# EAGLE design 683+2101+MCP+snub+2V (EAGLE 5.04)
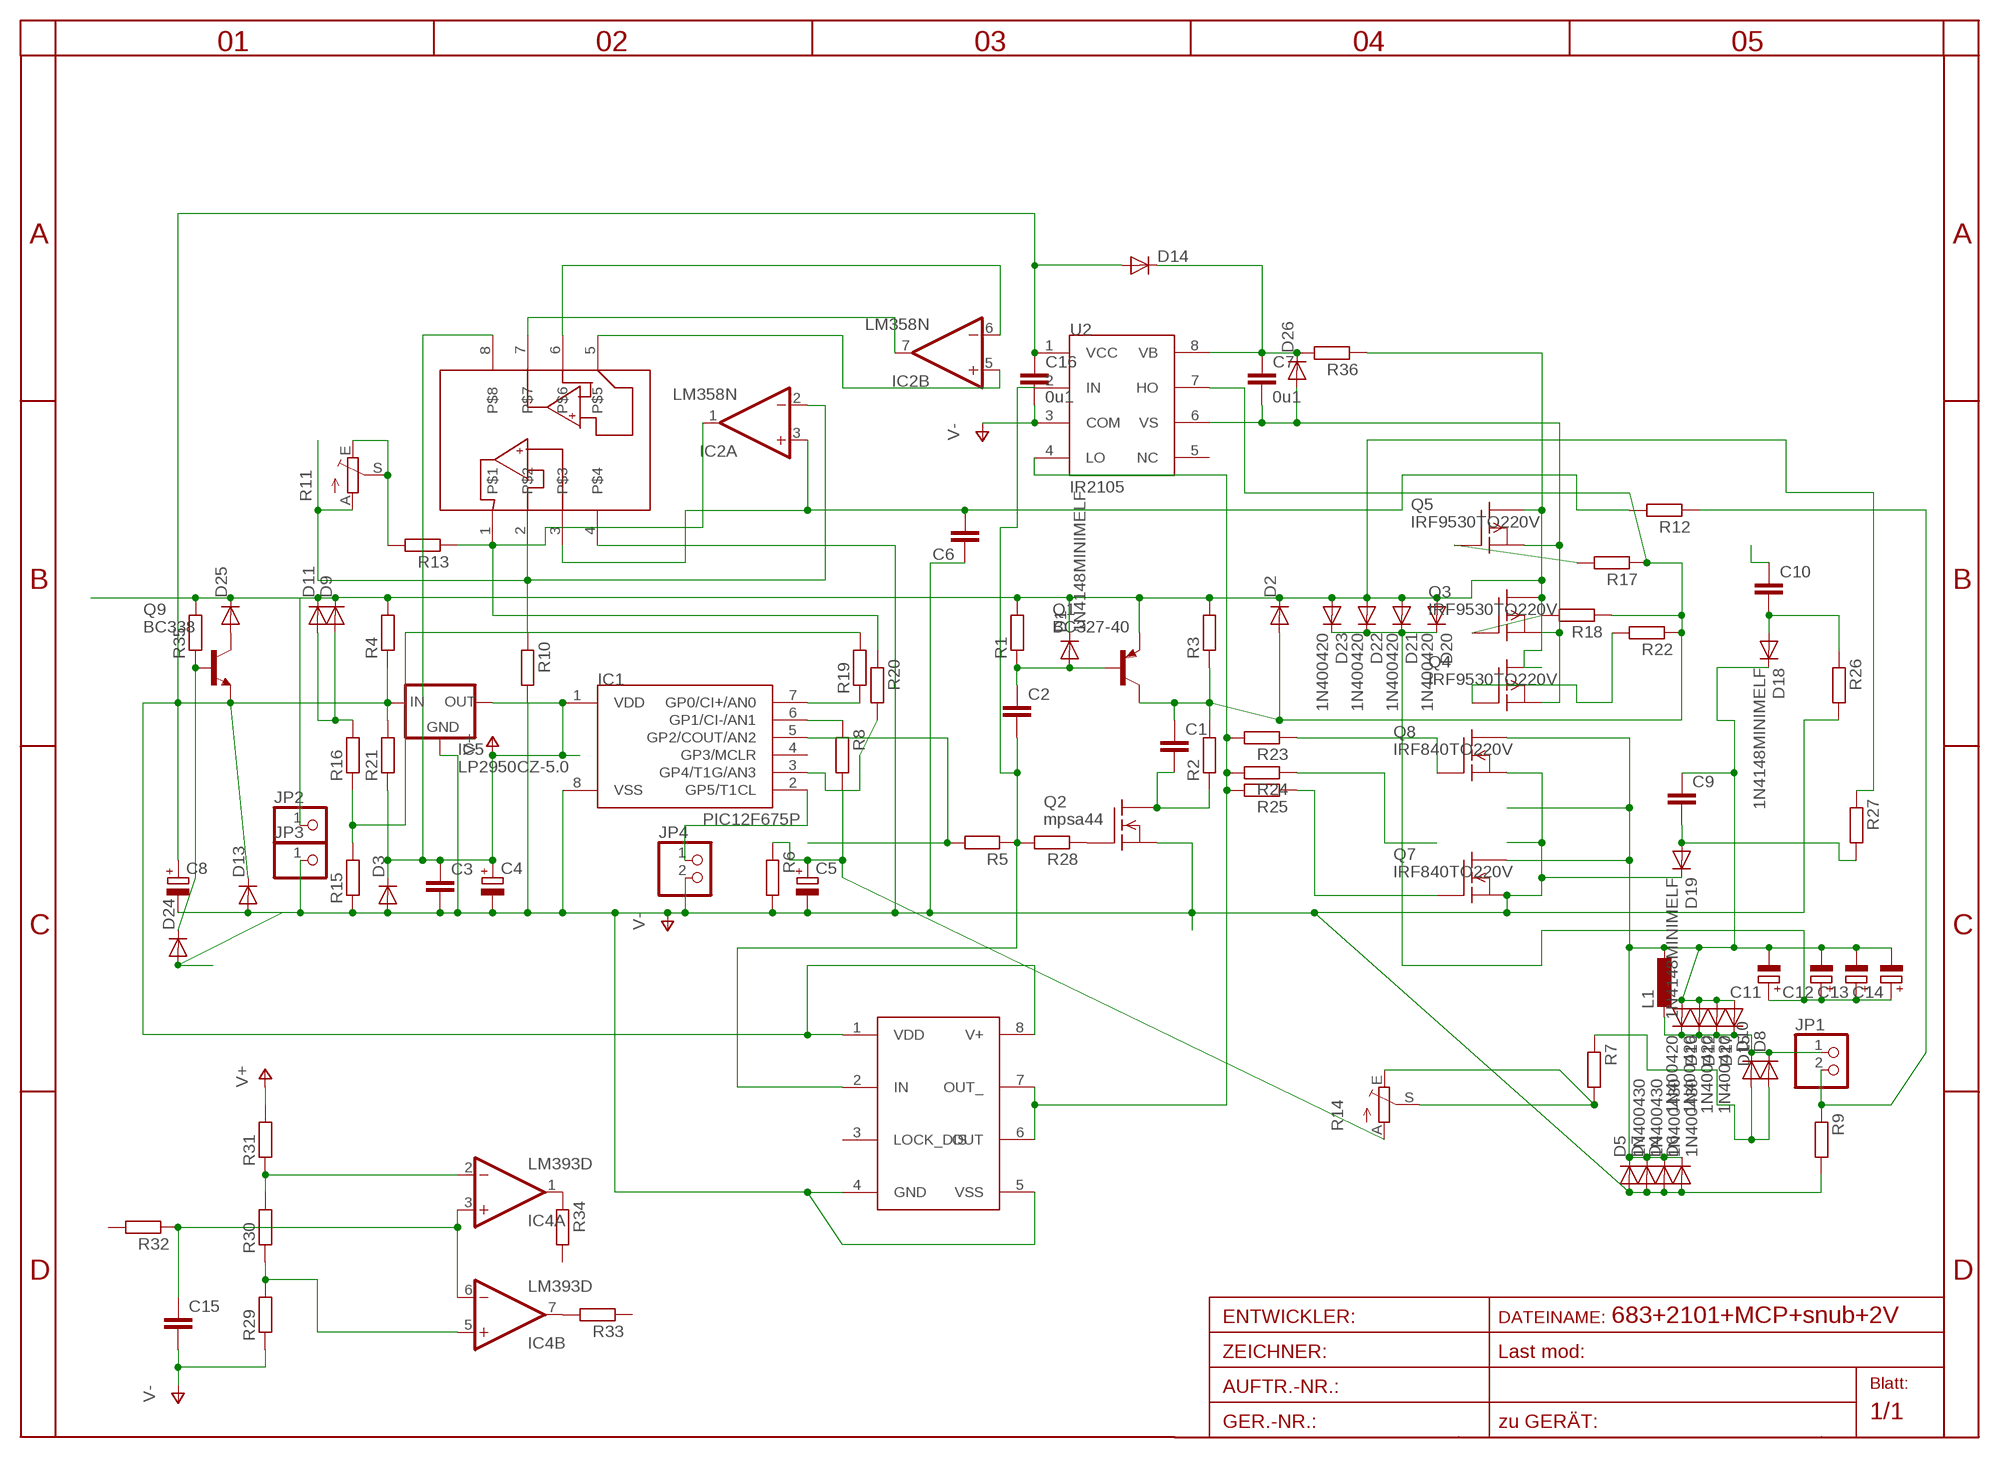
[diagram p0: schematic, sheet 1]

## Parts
C1  C-EU225-074X268  [C225-074X268]
C2  C-EU225-062X268  [C225-062X268]
C3  C-EU050-025X075  [C050-025X075]
C4  CPOL-EUE2.5-7  [E2,5-7]
C5  CPOL-EU5-13  [2,5-5-FLAT]
C6  C-EU025_050-025X075  [C025_050-025X075]
C7  0u1  C-EU050-030X075  [C050-030X075]
C8  CPOL-EU5-13  [2,5-5-FLAT]
C9  C-EUC1812  [C1812]
C10  C-EUC1812K  [C1812K]
C11  CPOL-EUSANYO_SMD_E7  [SANYO-OSCON_SMD_E7]
C12  CPOL-EUSANYO_SMD_E7  [SANYO-OSCON_SMD_E7]
C13  CPOL-EUSANYO_SMD_E7  [SANYO-OSCON_SMD_E7]
C14  CPOL-EUSANYO_SMD_E7  [SANYO-OSCON_SMD_E7]
C15  C-EU025-025X050  [C025-025X050]
C16  0u1  C-EU050-030X075  [C050-030X075]
D1  1N4148MINIMELF  [MINIMELF]
D2  DIODE-D-5  [D-5]
D3  DIODE-D-2.5  [D-2.5]
D4  1N400430  [DO41-30]
D5  1N400430  [DO41-30]
D6  1N400430  [DO41-30]
D7  1N400430  [DO41-30]
D8  DIODE-D-2.5  [D-2.5]
D9  DIODE-D-2.5  [D-2.5]
D10  DIODE-DO41-30  [DO41-30]
D11  DIODE-D-10  [D-10]
D12  1N400420  [DO41-20]
D13  DIODE-D-2.5  [D-2.5]
D14  DIODE-D-5  [D-5]
D15  1N400420  [DO41-20]
D16  1N400420  [DO41-20]
D17  1N400420  [DO41-20]
D18  1N4148MINIMELF  [MINIMELF]
D19  1N4148MINIMELF  [MINIMELF]
D20  1N400420  [DO41-20]
D21  1N400420  [DO41-20]
D22  1N400420  [DO41-20]
D23  1N400420  [DO41-20]
D24  DIODE-D-2.5  [D-2.5]
D25  DIODE-D-2.5  [D-2.5]
D26  DIODE-D-2.5  [D-2.5]
IC1  PIC12F675P  [DIL8]
IC2  LM358N  [DIL08]
IC3  TC4432X  [SO-08]
IC4  LM393D  [SO08]
IC5  LP2950CZ-5.0  [TO92]
JP1  PINHD-1X2  [1X02]
JP2  PINHD-1X1  [1X01]
JP3  PINHD-1X1  [1X01]
JP4  PINHD-1X2  [1X02]
L1  L-EU0204/7  [0204/7]
Q1  BC327-40  [TO92-EBC]
Q2  mpsa44  TN0604N3  [TO-92]
Q3  IRF9530TO220V  [TO220V]
Q4  IRF9530TO220V  [TO220V]
Q5  IRF9530TO220V  [TO220V]
Q7  IRF840TO220V  [TO220V]
Q8  IRF840TO220V  [TO220V]
Q9  BC338  [TO92-EBC]
R1  R-EU_0204/2V  [0204V]
R2  R-EU_0207/25  [0207/25]
R3  R-EU_0204/2V  [0204V]
R4  R-EU_0207/10  [0207/10]
R5  R-EU_0207/40  [0207/40]
R6  R-EU_0207/10  [0207/10]
R7  R-EU_0207/15  [0207/15]
R8  R-EU_0207/10  [0207/10]
R9  R-EU_0207/10  [0207/10]
R10  R-EU_0207/15  [0207/15]
R11  TRIM_EU-CIP20C-4MM  [CIP20C-4MM]
R12  R-EU_0207/30  [0207/30]
R13  R-EU_0207/40  [0207/40]
R14  TRIM_EU-CIP20C-4MM  [CIP20C-4MM]
R15  R-EU_0204/5  [0204/5]
R16  R-EU_0207/25  [0207/25]
R17  R-EU_R1206  [R1206]
R18  R-EU_R1206  [R1206]
R19  R-EU_0204/5  [0204/5]
R20  R-EU_0204/5  [0204/5]
R21  R-EU_0207/10  [0207/10]
R22  R-EU_R1206  [R1206]
R23  R-EU_R1206  [R1206]
R24  R-EU_R1206  [R1206]
R25  R-EU_R1206  [R1206]
R26  R-EU_0207/25  [0207/25]
R27  R-EU_0207/30  [0207/30]
R28  R-EU_R0805  [R0805]
R29  R-EU_0204/5  [0204/5]
R30  R-EU_0204/5  [0204/5]
R31  R-EU_0204/5  [0204/5]
R32  R-EU_0204/5  [0204/5]
R33  R-EU_0204/5  [0204/5]
R34  R-EU_0204/2V  [0204V]
R35  R-EU_0207/10  [0207/10]
R36  R-EU_0204/2V  [0204V]
U2  IR2105  [DIL08]
U$1  MCP6042SOIC  [SO-08]

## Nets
BB: C2.2 IC3.2(IN) R5.1 R28.2 U2.2(IN)
DRAIN: C9.1 C11.- C12.- C13.- C14.- D4.C D5.C D6.C D7.C D12.A D15.A D16.A D17.A D18.C L1.1 Q7.2(D) Q8.2(D)
GATE: C1.1 D2.A Q1.C R2.2 R3.1 R17.1 R18.1 R22.1 U2.7(HO)
MPOINT: C5.+ R6.1 R8.2 R14.A
N$1: C1.2 Q2.3(D) R2.1
N$2: IC2.6(B:-IN) U$1.6
N$3: IC1.5(GP2/COUT/AN2) R5.2
N$4: Q3.1(G) R18.2
N$5: IC1.6(GP1/CI-/AN1) R8.1
N$6: IC2.2(A:-IN) R10.1 R11.A U$1.2
N$7: IC2.1(A:OUT) R13.1 R20.1 U$1.1
N$8: Q2.2(G) R28.1
N$9: C6.2 IC2.3(A:+IN) R12.2 U$1.3
N$10: R7.2 R14.E R14.S
N$11: Q5.1(G) R17.2
N$12: R15.2 R16.1 R19.2
N$13: D9.A D11.A R16.2
N$14: IC1.7(GP0/CI+/AN0) R19.1
N$15: IC1.2(GP5/T1CL) JP4.1
N$16: D8.A D10.A R7.1
N$17: IC1.3(GP4/T1G/AN3) R20.2
N$18: IC2.5(B:+IN) U$1.5
N$19: C15.1 IC4.3(A:+IN) IC4.6(B:-IN) R32.1
N$20: IC2.7(B:OUT) U$1.7
N$21: C7.2 D26.A Q3.3(S) Q4.3(S) Q5.3(S) U2.6(VS)
N$22: IC4.7(B:OUT) R33.2
N$23: Q4.1(G) R22.2
N$24: C10.2 D18.A R26.1
N$25: Q7.1(G) R25.1
N$26: R24.1
N$27: Q8.1(G) R23.1
N$28: C9.2 D19.A R27.2
N$29: R11.E R11.S R13.2
N$30: IC4.1(A:OUT) R34.1
N$31: C11.+ C12.+ C13.+ C14.+ D20.C D21.C D22.C D23.C
N$32: IC4.5(B:+IN) R29.2 R30.1
N$33: IC3.6(OUT) IC3.7(OUT_) R23.2 R24.2 R25.2 U2.4(LO)
N$34: IC4.2(A:-IN) R30.2 R31.1
N$35: D25.A Q9.C
N$36: D24.C Q9.B R35.1
N$37: C10.1
OUT+: D8.C D10.C D12.C D15.C D16.C D17.C JP1.1 L1.2
OUT-: JP1.2 R9.1 R12.1
TB: C2.1 D1.A Q1.B R1.1
V+: C3.1 C4.+ D3.C IC1.1(VDD) IC5.1(OUT) R21.1 R31.2 U$1.8
V-: C3.2 C4.- C5.- C6.1 C8.- C15.2 C16.2 D3.A D4.A D5.A D6.A D7.A D13.A D19.C D24.A IC1.8(VSS) IC3.4(GND) IC3.5(VSS) IC5.2(GND) JP3.1 JP4.2 Q2.1(S) Q7.3(S) Q8.3(S) R6.2 R9.2 R10.2 R15.1 R26.2 R29.1 U2.3(COM) U$1.4
VB: C7.1 D14.C D26.C R36.2 U2.8(VB)
VCC: C8.+ C16.1 D13.C D14.A IC3.1(VDD) IC3.8(V+) IC5.3(IN) Q9.E R4.1 R21.2 U2.1(VCC)
VIN: D1.C D2.C D9.C D11.C D20.A D21.A D22.A D23.A JP2.1 Q1.E Q3.2(D) Q4.2(D) Q5.2(D) R1.2 R3.2 R4.2 R27.1 R36.1
VIN1: D25.C R35.2
Unconnected: IC1.4(GP3/MCLR) IC3.3(LOCK_DIS) R32.2 R33.1 R34.2 U2.5(NC)

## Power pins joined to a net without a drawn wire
V+: IC2.8(P:V+) IC4.8(P:V+)
V-: IC2.4(P:V-) IC4.4(P:V-)

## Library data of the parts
C1-C3 C6 C7 C9 C10 C15 C16 = rcl-2:C-EU: CAPACITOR, European symbol
C4 C5 C8 C11-C14 = rcl-2:CPOL-EU: POLARIZED CAPACITOR, European symbol
D1 D18 D19 = diode-1:1N4148: DIODE
D2 D3 D8-D11 D13 D14 D24-D26 = diode-1:DIODE-: DIODE
D4-D7 D12 D15-D17 D20-D23 = diode-1:1N4004: DIODE
IC1 = microchip-5:PIC12F6*: uPC nW 1k Program Flash memory 2x Timer Comparator 10b A/D converter/ 4xIN
IC2 = linear:LM358: OP AMP also LM158; LM258; LM2904 Source: http://cache.national.com/ds/LM/LM158.pdf
IC3 = microchip:TC4432
IC4 = linear:LM393: COMPARATOR
IC5 = v-reg:LP2950?*: Source: http://cache.national.com/ds/LP/LP2950.pdf
JP1 JP4 = pinhead:PINHD-1X2: PIN HEADER
JP2 JP3 = pinhead:PINHD-1X1: PIN HEADER
L1 = rcl-2:L-EU: INDUCTOR, European symbol
Q1 = transistor-pnp:BC327*: PNP Transistror
Q2 = transistor-fet:TN0604N3: N-Channel Enhancement MOSFET 40V; 4A; 0,75Ohm
Q3-Q5 = transistor-fet:IRF9530: P-Channel Enhancement MOSFET (HEXFET); -100V; -12A; 0,3Ohm
Q7 Q8 = transistor-fet:IRF840: N-Channel Enhancement MOSFET (HEXFET); 500V; 8A; 0,85Ohm
Q9 = transistor-npn:BC338*: NPN Transistor
R1-R10 R12 R13 R15-R36 = rcl-2:R-EU_: RESISTOR, European symbol
R11 R14 = pot:TRIM_EU-: POTENTIOMETER
U2 = irf-2:IR2105: Half bridge driver
U$1 = microchip-3:MCP6042

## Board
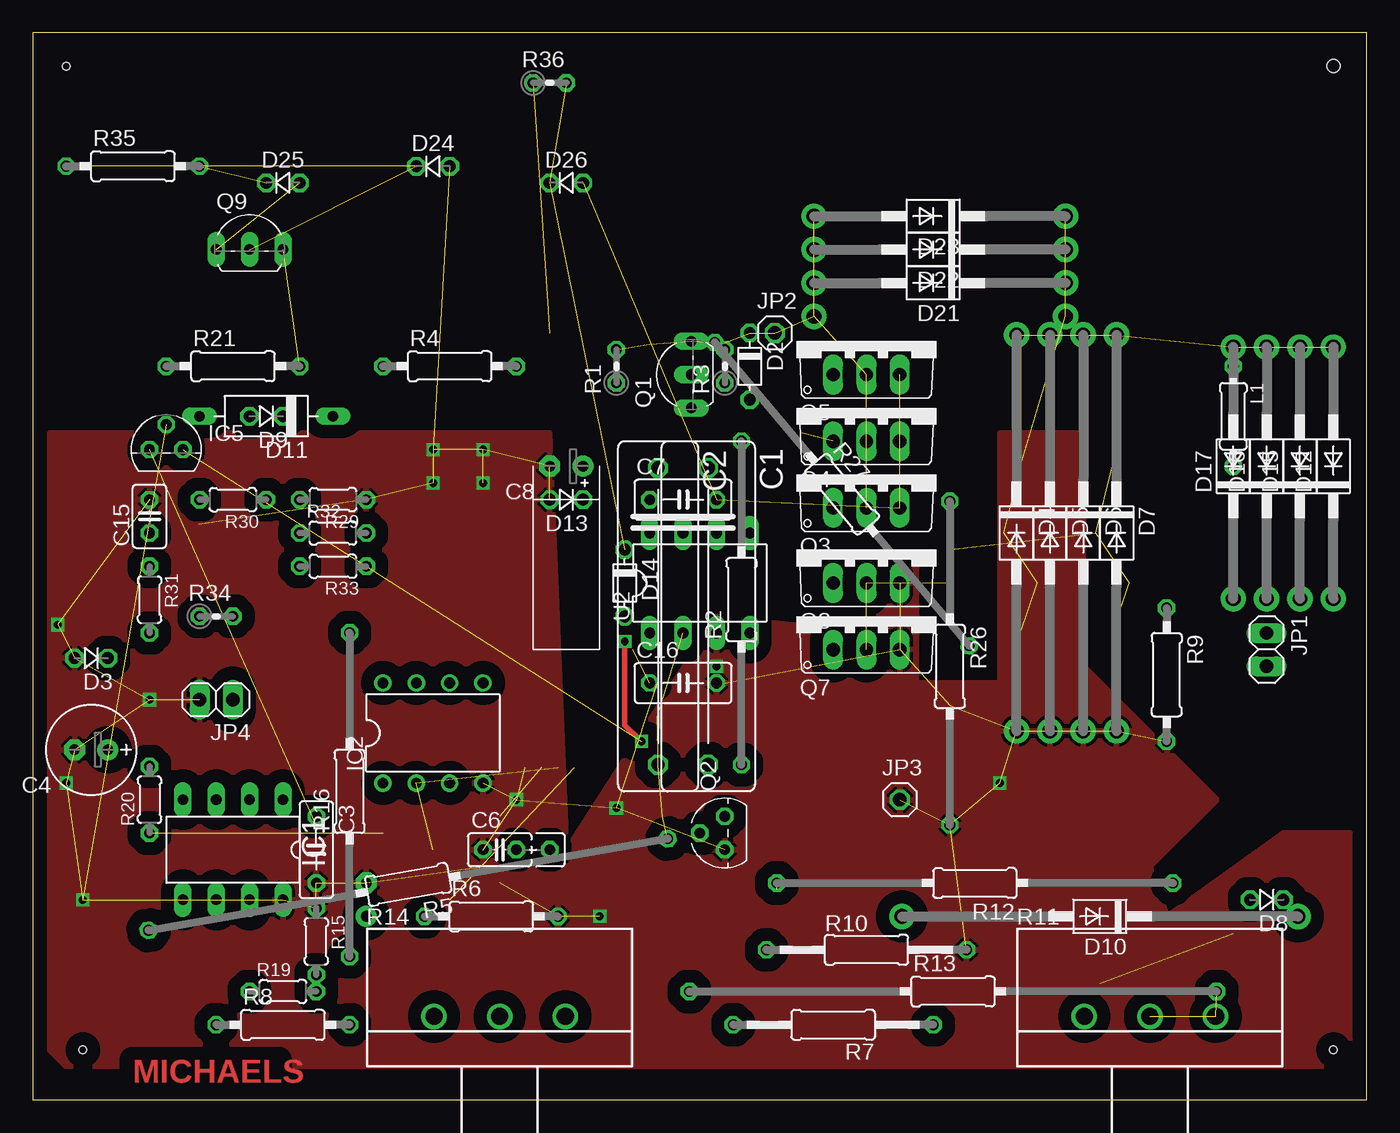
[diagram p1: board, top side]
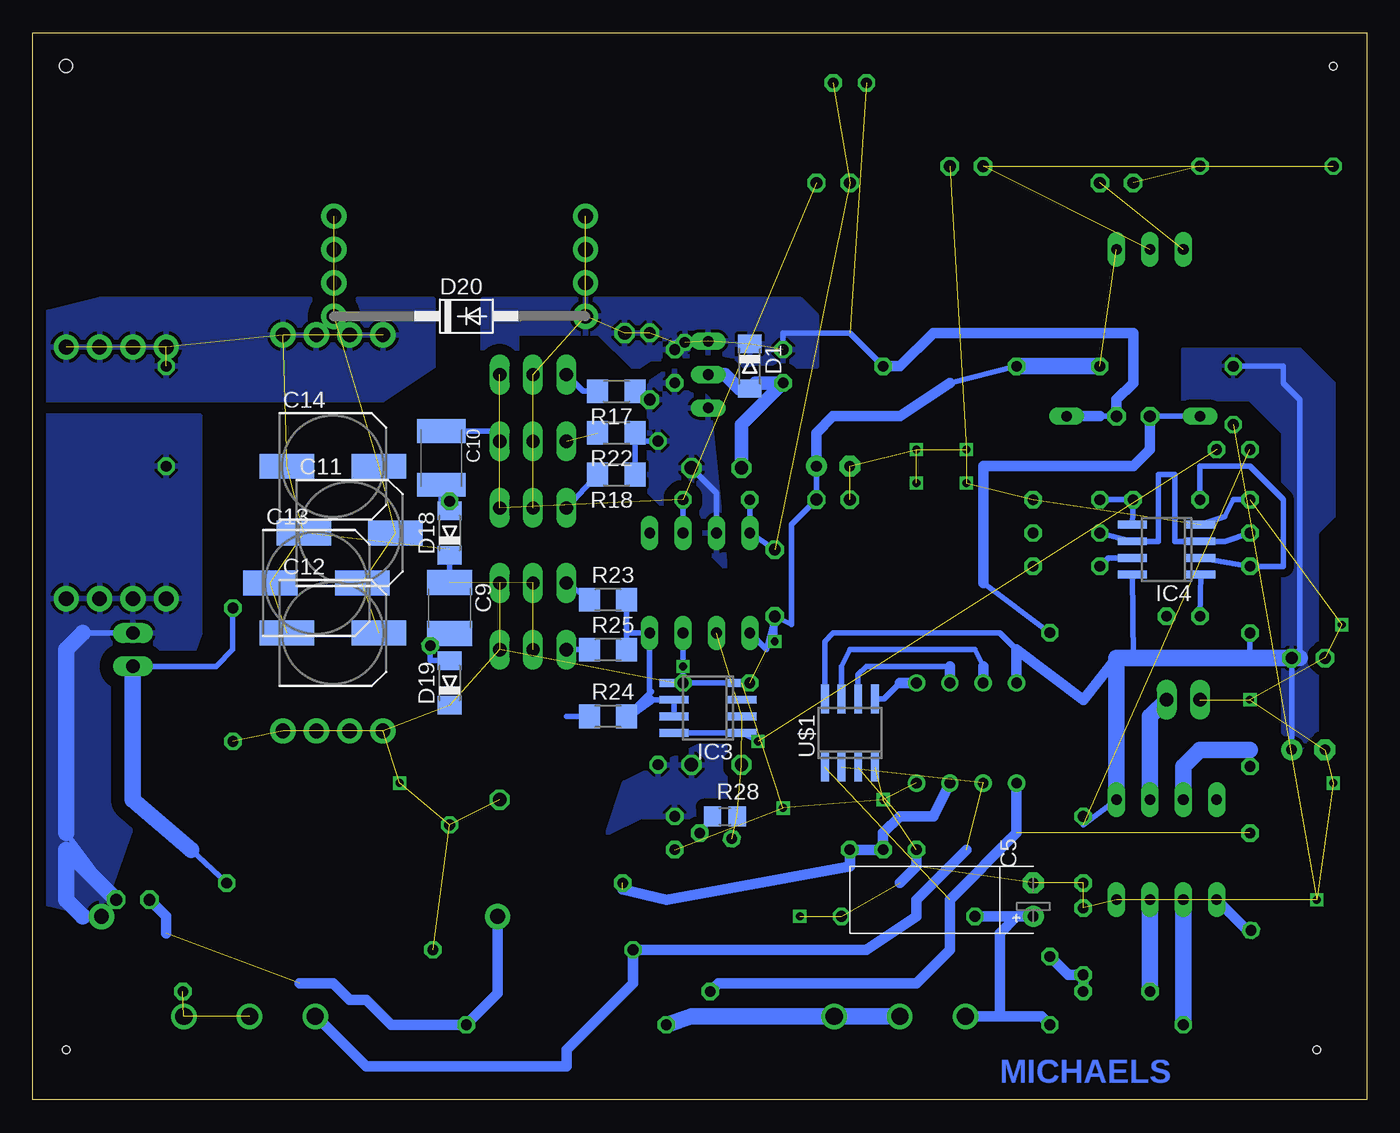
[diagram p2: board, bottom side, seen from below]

Size 101.6 x 81.28 mm. Coordinates in mm from the lower left corner, seen from the top.
Outline: 0,0 101.6,0 101.6,81.28 0,81.28 0,0
Copper layers (1*16): Top 0.035mm / dielectric 1.5mm / Bottom 0.035mm
Design rules "default": minimum track width 10mil, minimum drill 24mil, track to track 8mil, track to pad 8mil, pad to pad 8mil, via to via 8mil, smd to smd 8mil, copper to edge 40mil, drill to drill 8mil, minimum pad ring 10mil, minimum via ring 8mil, stop-mask expansion 4mil, vias tented up to drill 0mil, thermal gap 10mil
Holes 0.6 mm at 2.54,78.74 3.81,3.81 99.06,3.81
Holes 1 mm at 99.06,78.74

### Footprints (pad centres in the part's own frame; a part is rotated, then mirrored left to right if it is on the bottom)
C225-074X268 = drill 1.016 octagon: 1 -11.303,0; 2 11.303,0
C225-062X268 = drill 1.016 octagon: 1 -11.303,0; 2 11.303,0
C050-025X075 = drill 0.813 octagon: 1 -2.54,0; 2 2.54,0
E2,5-7 = drill 0.813 pad 1.6 round: + -1.27,0 | drill 0.813 pad 1.6 octagon: - 1.27,0
2,5-5-FLAT = drill 0.813 pad 1.6 round: + -1.27,0 | drill 0.813 pad 1.6 octagon: - 1.27,0
C025_050-025X075 = drill 0.813 octagon: 1 -1.27,0; 2 1.27,0; 3 3.81,0
C050-030X075 = drill 0.813 octagon: 1 -2.54,0; 2 2.54,0
C1812 = smd 1.9 x 3.4: 1 -1.95,0; 2 1.95,0
C1812K = smd 1.8 x 3.7: 1 -2.05,0; 2 2.05,0
SANYO-OSCON_SMD_E7 = smd 4.15 x 1.9: + 3.5,0; - -3.5,0
C025-025X050 = drill 0.813 octagon: 1 -1.27,0; 2 1.27,0
MINIMELF = smd 1.4 x 1.8: A 1.7,0; C -1.7,0
D-5 = drill 0.9 octagon: A 2.54,0; C -2.54,0
D-2.5 = drill 0.9 octagon: A 1.27,0; C -1.27,0
DO41-30 = drill 1.118 pad 1.93 round: A 15.08,0; C -15.08,0
D-10 = drill 0.813 long: A 5.08,0; C -5.08,0
DO41-20 = drill 1.118 pad 1.93 round: A 9.08,0; C -10.08,0
DIL8 = drill 0.813 long: 1 -3.81,-3.81; 2 -1.27,-3.81; 3 1.27,-3.81; 4 3.81,-3.81; 5 3.81,3.81; 6 1.27,3.81; 7 -1.27,3.81; 8 -3.81,3.81
DIL08 = drill 0.813 pad 1.27 round: 1 -3.81,-3.81; 2 -1.27,-3.81; 3 1.27,-3.81; 4 3.81,-3.81; 5 3.81,3.81; 6 1.27,3.81; 7 -1.27,3.81; 8 -3.81,3.81
SO-08 = smd 0.6 x 2.2: 1 -1.905,-2.6; 2 -0.635,-2.6; 3 0.635,-2.6; 4 1.905,-2.6; 5 1.905,2.6; 6 0.635,2.6; 7 -0.635,2.6; 8 -1.905,2.6
SO08 = smd 0.6 x 2.2: 1 -1.905,-2.6; 2 -0.635,-2.6; 3 0.635,-2.6; 4 1.905,-2.6; 5 1.905,2.6; 6 0.635,2.6; 7 -0.635,2.6; 8 -1.905,2.6
TO92 = drill 0.813 octagon: 1 -1.27,0; 2 0,1.905; 3 1.27,0
1X02 = drill 1.016 long: 1 -1.27,0; 2 1.27,0
1X01 = drill 1.016 octagon: 1 0,0
0204/7 = drill 0.813 octagon: 1 -3.81,0; 2 3.81,0
TO92-EBC = drill 0.813 long: B 0,-1.27; C -2.54,-1.27; E 2.54,-1.27
TO-92 = drill 0.813 octagon: 1 -1.27,0; 2 0,1.905; 3 1.27,0
TO220V = drill 1.016 long: 1 -2.54,-2.54; 2 0,-2.54; 3 2.54,-2.54
0204V = drill 0.813 octagon: 1 -1.27,0; 2 1.27,0
0207/25 = drill 0.813 octagon: 1 -12.58,0; 2 12.08,0
0207/10 = drill 0.813 octagon: 1 -5.08,0; 2 5.08,0
0207/40 = drill 0.813 octagon: 1 -20.08,0; 2 20.08,0
0207/15 = drill 0.813 octagon: 1 -7.62,0; 2 7.62,0
CIP20C-4MM = drill 1.3 pad 1.93 round: A -5,0; E 5,0; S 0,0
0207/30 = drill 0.813 octagon: 1 -15.08,0; 2 15.08,0
0204/5 = drill 0.813 octagon: 1 -2.54,0; 2 2.54,0
R1206 = smd 1.6 x 1.803: 1 -1.422,0; 2 1.422,0
R0805 = smd 1.3 x 1.5: 1 -0.95,0; 2 0.95,0
DIL08' = drill 0.813 long: 1 -3.81,-3.81; 2 -1.27,-3.81; 3 1.27,-3.81; 4 3.81,-3.81; 5 3.81,3.81; 6 1.27,3.81; 7 -1.27,3.81; 8 -3.81,3.81

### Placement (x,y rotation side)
C1  51.44,36.83 270 top
C2  47.62,36.83 270 top
C3  21.59,19.05 270 top
C4  4.45,26.67 180 top
C5  25.4,15.24 90 bottom
C6  35.56,19.05 0 top
C7  49.53,45.72 0 top
C8  40.64,48.26 180 top
C9  69.85,37.47 270 bottom
C10  70.48,48.9 270 bottom
C11  77.47,43.18 0 bottom
C12  78.74,35.56 0 bottom
C13  80.01,39.37 0 bottom
C14  78.74,48.26 0 bottom
C15  8.89,44.45 90 top
C16  49.53,31.75 0 top
D1  46.99,55.88 270 bottom
D2  54.61,55.88 270 top
D3  4.45,33.66 180 top
D4  74.93,43.18 270 top
D5  77.47,43.18 270 top
D6  80.01,43.18 270 top
D7  82.55,43.18 270 top
D8  93.98,15.24 180 top
D9  17.78,52.07 180 top
D10  81.28,13.97 180 top
D11  17.78,52.07 180 top
D12  99.06,48.26 90 top
D13  40.64,45.72 180 top
D14  45.09,39.37 270 top
D15  96.52,48.26 90 top
D16  93.98,48.26 90 top
D17  91.44,48.26 90 top
D18  69.85,43.18 90 bottom
D19  69.85,31.75 90 bottom
D20  68.58,59.69 0 bottom
D21  68.58,62.23 180 top
D22  68.58,64.77 180 top
D23  68.58,67.31 180 top
D24  30.48,71.12 0 top
D25  19.05,69.85 0 top
D26  40.64,69.85 0 top
IC1  15.24,19.05 180 top
IC2  30.48,27.94 0 top
IC3  50.16,29.84 90 bottom
IC4  15.24,41.91 90 bottom
IC5  10.16,49.53 0 top
JP1  93.98,34.29 270 top
JP2  56.52,58.42 0 top
JP3  66.04,22.86 0 top
JP4  13.97,30.48 180 top
L1  91.44,52.07 270 top
Q1  48.9,55.24 90 top
Q2  52.7,20.32 90 top
Q3  63.5,47.62 0 top
Q4  63.5,52.7 0 top
Q5  63.5,57.78 0 top
Q7  63.5,36.83 0 top
Q8  63.5,41.91 0 top
Q9  16.51,66.04 0 top
R1  44.45,55.88 90 top
R2  53.98,38.1 90 top
R3  52.7,55.88 90 top
R4  31.75,55.88 0 top
R5  28.58,16.4 190 top
R6  34.92,13.97 0 top
R7  60.96,5.71 180 top
R8  19.05,5.71 0 top
R9  86.36,32.38 270 top
R10  63.5,11.43 0 top
R11  85.09,6.35 0 top
R12  71.75,16.51 180 top
R13  70.09,8.26 0 top
R14  35.56,6.35 0 top
R15  21.59,12.06 270 top
R16  24.13,23.5 90 top
R17  57.15,53.98 180 bottom
R18  57.15,47.62 180 bottom
R19  19.05,8.26 0 top
R20  8.89,22.86 90 top
R21  15.24,55.88 0 top
R22  57.15,50.8 180 bottom
R23  57.78,38.1 0 bottom
R24  57.78,29.21 0 bottom
R25  57.78,34.29 0 bottom
R26  69.85,33.02 270 top
R27  61.63,46.14 310 top
R28  48.9,21.59 0 bottom
R29  22.86,45.72 180 top
R30  15.24,45.72 180 top
R31  8.89,38.1 270 top
R32  22.86,43.18 0 top
R33  22.86,40.64 180 top
R34  13.97,36.83 0 top
R35  7.62,71.12 0 top
R36  39.37,77.47 0 top
U2  IR2105  [DIL08']  50.8,39.37 0 top
U$1  39.37,27.94 0 bottom

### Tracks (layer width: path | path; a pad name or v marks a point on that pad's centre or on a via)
BB  (4 unrouted)
DRAIN  (15 unrouted)
  Bottom 0.406: C9.1 D18.C 69.85,41.91
  pour Bottom (isolate 1.016, rank 5): 101.6,53.34 74.93,53.34 71.12,55.88 71.12,60.96 96.52,60.96 101.6,59.69
GATE
  Bottom 0.406: C1.1 49.53,46.23 U2.7 | R18.1 R22.1 55.11,50.18 R2.2 | D2.A 55.09,53.34 R17.1
  pour Bottom (isolate 0.813, rank 2): 50.16,53.34 52.7,55.88 54.61,54.61 54.61,46.35 48.9,40.64
MPOINT
  Bottom 0.813: R6.1 C5.+ 26.67,13.97 27.94,12.7 27.94,6.35 | 27.94,6.35 24.77,6.35 R8.2 | 27.94,6.35 R14.A
N$1
  pour Bottom (isolate 0.61, rank 3): 48.9,27.94 56.52,24.13 57.78,20.32 55.24,21.59 48.9,21.59
N$2
  Bottom 0.406: U$1.6 38.73,32.38 38.1,33.02 31.75,33.02
  Bottom 0.813: IC2.6 31.75,33.02
N$3
  Bottom 0.813: R5.2 9.1,12.91 IC1.5
N$4
  Bottom 0.406: R18.2 Q3.1
N$5
  Bottom 1.27: R8.1 IC1.6
N$6  (2 unrouted)
  Bottom 0.813: 30.48,19.05 34.29,15.24 34.29,13.97 38.1,11.43 R10.1 55.88,8.89 60.96,3.81 60.96,2.54 76.2,2.54 80.01,6.35 R11.A
N$7  (2 unrouted)
  Bottom 0.813: IC2.1 26.67,20.32 31.75,15.24 31.75,11.43 34.29,8.89 49.38,8.89 R13.1
N$8
  Bottom 0.406: R28.1 Q2.2
N$9  (2 unrouted)
  Bottom 0.813: 56.67,16.04 53.34,15.24 39.37,17.78 39.37,19.05 C6.2 36.83,20.32 35.56,21.59 33.02,21.59 IC2.3
N$10
  Bottom 1.27: R14.S R14.E 51.44,6.35 R7.2
N$11
  Bottom 0.406: R17.2 59.69,53.98 Q5.1
N$12
  Bottom 0.813: R19.2 R15.2 22.74,9.53 R16.1
N$13
  Bottom 0.406: D9.A D11.A | R16.2 29.2,39.37
  Bottom 0.813: D9.A 16.51,49.53 17.78,48.26 29.21,48.26 29.21,43.18 29.2,39.37
N$14
  Bottom 1.27: R19.1 IC1.7
N$15
  Bottom 1.27: IC1.2 16.51,29.21 JP4.1
N$16  (1 unrouted)
  Bottom 0.813: 81.28,8.89 78.74,8.89 77.47,7.62 76.2,7.62 74.3,5.71 R7.1 66.2,8.1 D10.A | 91.44,12.7 91.44,13.97 D8.A
N$17
  Bottom 0.406: R20.2 8.89,26.67
  Bottom 1.27: 8.89,26.67 12.7,26.67 13.97,25.4 IC1.3
N$18
  Bottom 0.406: U$1.5 36.77,30.54 35.56,31.75
  Bottom 0.813: IC2.5 35.56,31.75
N$19
  Bottom 0.406: C15.1 10.79,42.55 IC4.3 14.61,42.55 14.61,47.62 15.88,47.62 15.88,42.55 IC4.6 R32.1
N$20
  Bottom 0.406: U$1.7 40.01,33.02 39.37,34.29 29.84,34.29 29.21,33.02
  Bottom 0.813: IC2.7 29.21,33.02
N$21  (4 unrouted)
  Bottom 0.406: U2.6 C7.2
N$22
  Bottom 0.406: R33.2 19.68,41.27 IC4.7
N$23  (1 unrouted)
N$24
  Bottom 0.406: D18.A R26.1 70.48,45.6 C10.2
N$25
  Bottom 0.406: R25.1 Q7.1
N$26
  Bottom 0.406: R24.1 60.96,29.21
N$27
  Bottom 0.406: R23.1 Q8.1
N$28
  Bottom 0.406: C9.2 71.33,35.52 R27.2 71.33,33.45 D19.A
N$29  (2 unrouted)
N$30
  Bottom 0.406: R34.1 IC4.1
N$31  (7 unrouted)
N$32
  Bottom 0.406: IC4.5 R30.1 R29.2
N$33
  Bottom 0.406: 54.61,30.96 U2.4 56.36,35.56 | R24.2 54.61,30.96 | 56.36,35.56 R25.2 | 56.36,35.56 R23.2 | IC3.7 IC3.6 54.61,30.48 | 54.61,30.96 54.46,31.11
  Bottom 0.813: 54.61,30.48 R24.2
N$34
  Bottom 0.406: R30.2 12.7,48.26 8.89,48.26 6.35,45.72 6.35,40.64 R31.1 IC4.2
N$35  (1 unrouted)
N$36  (2 unrouted)
N$37
  Bottom 0.406: 66.04,50.95 C10.1
OUT+
  Bottom 0.406: 97.79,35.56 JP1.1 | D8.C 99.06,20.32 | D10.C 97.79,13.97
  Bottom 1.27: 97.79,35.56 99.06,34.29 99.06,20.32 | D8.C 99.06,19.05 99.06,15.24 97.79,13.97
  pour Bottom (isolate 1.016, rank 5): 88.9,52.07 101.6,52.07 101.6,15.24 96.52,13.97 88.9,35.56
OUT-
  Bottom 0.406: R12.1 89.53,19.05 | JP1.2 87.63,33.02 86.36,34.29 R9.1
  Bottom 1.27: 89.53,19.05 93.98,22.86 JP1.2
TB
  Bottom 1.016: C2.1 47.62,51.44 R1.1 46.56,54.61 D1.A 47.83,54.18 48.9,55.24 Q1.B
V+  (1 unrouted)
  Bottom 0.406: R21.1 6.35,55.88 6.35,54.61 5.08,53.34 5.08,34.29 | 5.08,34.29 D3.C C4.+ | 5.08,34.29 5.08,33.66 | IC1.1 21.59,20.95 C3.1 | U$1.8 41.27,34.92 40.64,35.56 27.94,35.56 26.67,34.29 | 17.78,33.66 IC4.8 | 8.89,33.66 R31.2
  Bottom 0.813: 19.05,33.66 21.59,30.48 26.67,34.29 IC2.8
  Bottom 1.27: 5.08,33.66 D3.C 8.89,33.66 17.78,33.66 19.05,33.66 IC1.1
  pour Bottom (isolate 0.61, rank 3): 13.97,57.15 5.08,57.15 2.54,54.61 2.54,44.45 3.81,43.18 3.81,27.94 5.08,26.67 6.35,27.94 6.35,50.8 8.89,53.34 13.97,53.34
V-  (via drill 0.6)  (41 unrouted)
  Bottom 0.406: IC3.4 C16.2 | C16.2 IC3.5 | C16.2 v52.07,33.02 U2.3 | IC4.4 10.79,44.45 10.16,45.72 C15.2
  Bottom 0.813: C6.1 34.29,17.78 35.56,16.51
  other vias: 36.83,22.86 44.45,22.23 43.18,13.97 73.66,24.13 8.89,30.48 30.48,49.53 34.29,49.53 34.29,46.99 30.48,46.99 1.91,36.2 2.54,24.13 3.81,15.24
  pour Top (isolate 1.016, rank 5): 1.27,50.8 39.37,50.8 40.64,19.05 52.07,36.83 63.5,35.56 64.77,40.64 67.31,40.64 67.31,31.75 73.66,31.75 73.66,50.8 80.01,50.8 80.01,33.02 90.17,22.86 85.09,17.78 86.36,13.97 95.25,20.32 100.33,20.32 100.33,3.81 99.06,2.54 2.54,2.54 1.27,3.81
VB  (2 unrouted)
  Bottom 0.406: C7.1 U2.8 D14.C
VCC  (via drill 0.6)  (3 unrouted)
  Top 0.406: v46.35,27.3 45.09,28.57 v45.09,34.92
  Bottom 0.406: D14.A 43.81,36.2 43.81,43.81 D13.C C8.+ | 31.75,54.61 R4.1 | D14.A 45.72,34.29 U2.1 | IC3.8 IC3.1 v46.35,27.3 | v45.09,34.92 D14.A
  Bottom 0.813: 31.75,54.61 35.56,52.07 40.64,52.07 41.91,50.8 C8.+
  Bottom 1.27: R4.1 R21.2
VIN  (13 unrouted)
  Bottom 0.406: D9.C 20.32,52.07 | R4.2 39.37,58.42 44.45,58.42 R1.2 | R27.1 52.7,57.69 R3.2
  Bottom 0.813: 20.32,52.07 D11.C | R4.2 35.56,55.88 33.02,58.42 17.78,58.42 17.78,54.61 19.05,53.34 D9.C
  pour Bottom (isolate 0.813, rank 3): 67.31,43.18 67.31,60.96 43.18,60.96 41.91,59.69 41.91,55.88 55.88,55.88 58.42,58.42 64.77,58.42 64.77,44.45 66.04,43.18
VIN1  (1 unrouted)

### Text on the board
Top: MICHAELS
Bottom: MICHAELS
